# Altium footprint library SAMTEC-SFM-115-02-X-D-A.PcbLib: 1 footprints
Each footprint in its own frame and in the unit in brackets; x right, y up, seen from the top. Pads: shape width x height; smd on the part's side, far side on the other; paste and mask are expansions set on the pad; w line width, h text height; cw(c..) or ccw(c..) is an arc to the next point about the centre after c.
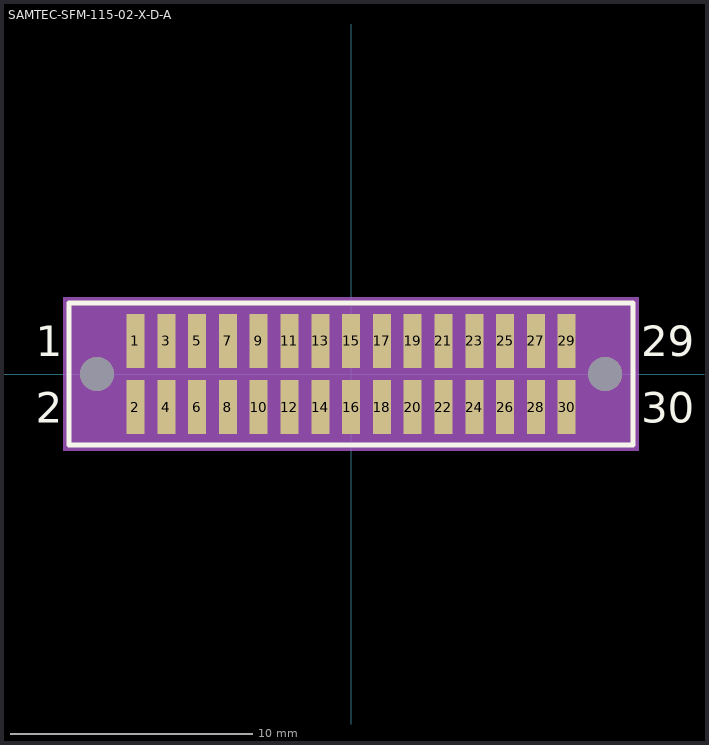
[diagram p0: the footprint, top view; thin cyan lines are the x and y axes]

## SAMTEC-SFM-115-02-X-D-A [mm]
pads (32):
  rect 0.74x2.22 smd mask+0: 1(-8.89,1.365) 2(-8.89,-1.365) 3(-7.62,1.365) 4(-7.62,-1.365) 5(-6.35,1.365) 6(-6.35,-1.365) 7(-5.08,1.365) 8(-5.08,-1.365) 9(-3.81,1.365) 10(-3.81,-1.365) 11(-2.54,1.365) 12(-2.54,-1.365) 13(-1.27,1.365) 14(-1.27,-1.365) 15(0,1.365) 16(0,-1.365) 17(1.27,1.365) 18(1.27,-1.365) 19(2.54,1.365) 20(2.54,-1.365) 21(3.81,1.365) 22(3.81,-1.365) 23(5.08,1.365) 24(5.08,-1.365) 25(6.35,1.365) 26(6.35,-1.365) 27(7.62,1.365) 28(7.62,-1.365) 29(8.89,1.365) 30(8.89,-1.365)
  round 1.4 hole 1.4 unplated: ""(-10.478,0) ""(10.478,0)
Top Overlay:
  lines w0.2: -11.629,-2.926 -11.629,2.926 11.629,2.926 11.629,-2.926 -11.629,-2.926
  text "2" at -12.999,-2 h1.27
  text "1" at -12.999,0.73 h1.27
  text "30" at 11.969,-2 h1.27
  text "29" at 11.969,0.73 h1.27
Top Paste:
  region: -8.52,0.255 -9.26,0.255 -9.26,2.475 -8.52,2.475
  region: -8.52,-2.475 -9.26,-2.475 -9.26,-0.255 -8.52,-0.255
  region: -7.25,0.255 -7.99,0.255 -7.99,2.475 -7.25,2.475
  region: -7.25,-2.475 -7.99,-2.475 -7.99,-0.255 -7.25,-0.255
  region: -5.98,0.255 -6.72,0.255 -6.72,2.475 -5.98,2.475
  region: -5.98,-2.475 -6.72,-2.475 -6.72,-0.255 -5.98,-0.255
  region: -4.71,0.255 -5.45,0.255 -5.45,2.475 -4.71,2.475
  region: -4.71,-2.475 -5.45,-2.475 -5.45,-0.255 -4.71,-0.255
  region: -3.44,0.255 -4.18,0.255 -4.18,2.475 -3.44,2.475
  region: -3.44,-2.475 -4.18,-2.475 -4.18,-0.255 -3.44,-0.255
  region: -2.17,0.255 -2.91,0.255 -2.91,2.475 -2.17,2.475
  region: -2.17,-2.475 -2.91,-2.475 -2.91,-0.255 -2.17,-0.255
  region: -0.9,0.255 -1.64,0.255 -1.64,2.475 -0.9,2.475
  region: -0.9,-2.475 -1.64,-2.475 -1.64,-0.255 -0.9,-0.255
  region: 0.37,0.255 -0.37,0.255 -0.37,2.475 0.37,2.475
  region: 0.37,-2.475 -0.37,-2.475 -0.37,-0.255 0.37,-0.255
  region: 1.64,0.255 0.9,0.255 0.9,2.475 1.64,2.475
  region: 1.64,-2.475 0.9,-2.475 0.9,-0.255 1.64,-0.255
  region: 2.91,0.255 2.17,0.255 2.17,2.475 2.91,2.475
  region: 2.91,-2.475 2.17,-2.475 2.17,-0.255 2.91,-0.255
  region: 4.18,0.255 3.44,0.255 3.44,2.475 4.18,2.475
  region: 4.18,-2.475 3.44,-2.475 3.44,-0.255 4.18,-0.255
  region: 5.45,0.255 4.71,0.255 4.71,2.475 5.45,2.475
  region: 5.45,-2.475 4.71,-2.475 4.71,-0.255 5.45,-0.255
  region: 6.72,0.255 5.98,0.255 5.98,2.475 6.72,2.475
  region: 6.72,-2.475 5.98,-2.475 5.98,-0.255 6.72,-0.255
  region: 7.99,0.255 7.25,0.255 7.25,2.475 7.99,2.475
  region: 7.99,-2.475 7.25,-2.475 7.25,-0.255 7.99,-0.255
  region: 9.26,0.255 8.52,0.255 8.52,2.475 9.26,2.475
  region: 9.26,-2.475 8.52,-2.475 8.52,-0.255 9.26,-0.255
Top Solder:
  circle w0: c10.478,0 r0.751
  circle w0: c-10.478,0 r0.751
  region: -8.469,0.204 -9.311,0.204 -9.311,2.526 -8.469,2.526
  region: -8.469,-2.526 -9.311,-2.526 -9.311,-0.204 -8.469,-0.204
  region: -7.199,0.204 -8.041,0.204 -8.041,2.526 -7.199,2.526
  region: -7.199,-2.526 -8.041,-2.526 -8.041,-0.204 -7.199,-0.204
  region: -5.929,0.204 -6.771,0.204 -6.771,2.526 -5.929,2.526
  region: -5.929,-2.526 -6.771,-2.526 -6.771,-0.204 -5.929,-0.204
  region: -4.659,0.204 -5.501,0.204 -5.501,2.526 -4.659,2.526
  region: -4.659,-2.526 -5.501,-2.526 -5.501,-0.204 -4.659,-0.204
  region: -3.389,0.204 -4.231,0.204 -4.231,2.526 -3.389,2.526
  region: -3.389,-2.526 -4.231,-2.526 -4.231,-0.204 -3.389,-0.204
  region: -2.119,0.204 -2.961,0.204 -2.961,2.526 -2.119,2.526
  region: -2.119,-2.526 -2.961,-2.526 -2.961,-0.204 -2.119,-0.204
  region: -0.849,0.204 -1.691,0.204 -1.691,2.526 -0.849,2.526
  region: -0.849,-2.526 -1.691,-2.526 -1.691,-0.204 -0.849,-0.204
  region: 0.421,0.204 -0.421,0.204 -0.421,2.526 0.421,2.526
  region: 0.421,-2.526 -0.421,-2.526 -0.421,-0.204 0.421,-0.204
  region: 1.691,0.204 0.849,0.204 0.849,2.526 1.691,2.526
  region: 1.691,-2.526 0.849,-2.526 0.849,-0.204 1.691,-0.204
  region: 2.961,0.204 2.119,0.204 2.119,2.526 2.961,2.526
  region: 2.961,-2.526 2.119,-2.526 2.119,-0.204 2.961,-0.204
  region: 4.231,0.204 3.389,0.204 3.389,2.526 4.231,2.526
  region: 4.231,-2.526 3.389,-2.526 3.389,-0.204 4.231,-0.204
  region: 5.501,0.204 4.659,0.204 4.659,2.526 5.501,2.526
  region: 5.501,-2.526 4.659,-2.526 4.659,-0.204 5.501,-0.204
  region: 6.771,0.204 5.929,0.204 5.929,2.526 6.771,2.526
  region: 6.771,-2.526 5.929,-2.526 5.929,-0.204 6.771,-0.204
  region: 8.041,0.204 7.199,0.204 7.199,2.526 8.041,2.526
  region: 8.041,-2.526 7.199,-2.526 7.199,-0.204 8.041,-0.204
  region: 9.311,0.204 8.469,0.204 8.469,2.526 9.311,2.526
  region: 9.311,-2.526 8.469,-2.526 8.469,-0.204 9.311,-0.204
Bottom Solder:
  circle w0: c10.478,0 r0.751
  circle w0: c-10.478,0 r0.751
Mechanical 15:
  region: 11.864,-3.161 -11.864,-3.161 -11.864,3.161 11.864,3.161
3D body "SFM-115-02-L-D-A.stp": height 4.7, standoff -1.14, extent -11.112,-2.159 11.112,2.045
